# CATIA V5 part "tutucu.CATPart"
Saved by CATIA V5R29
Part number: tutucu
Revision: HERHANG?
Definition: B??MEYEN
Nomenclature: tutucu
Source: Unknown
Bounding box of the stored display mesh (mm): x -579.422 to -391.883, y -310.528 to 310.528, z -100 to 77.537
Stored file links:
  C:\Users\제5강의실-27\Desktop\가치같이_내작업\tutucu.CATPart
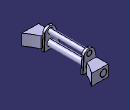
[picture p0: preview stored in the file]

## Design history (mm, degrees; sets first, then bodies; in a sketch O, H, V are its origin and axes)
Body1 "Kes-Ekstr?yon3" (main body)
  Solid1: solid without history
Body2 "Kes-Ekstr?yon4"
  Solid2: solid without history
Body3 "Radyus4"
  Solid3: solid without history
Body4 "Aynalama2"
  Solid4: solid without history
Body5 "Y?seklik-Ekstr?yon9"
  Solid5: solid without history
Body6 "Y?seklik-Ekstr?yon10"
  Solid6: solid without history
